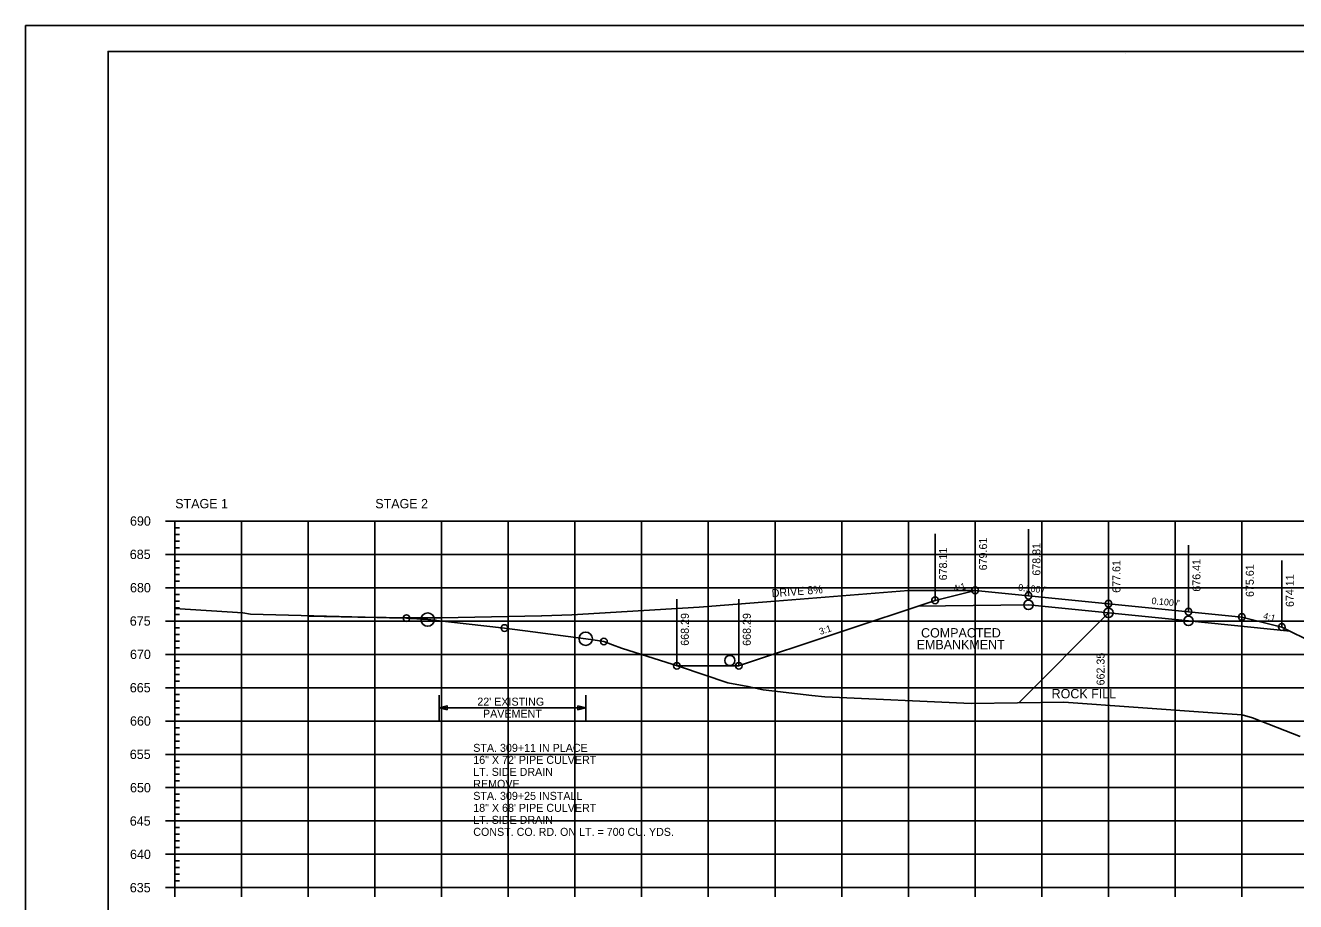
# Model space of a CAD drawing. Extents: x 1370515 to 1370849, y 383299 to 386073.
# Drawn here: x 1370515.4 to 1370705.9, y 384661.3 to 384792.8 of the extents above; entities that cross this region are included whole.
import ezdxf

# ---------------------------------------------------------------- set-up
doc = ezdxf.new("R2010")
doc.units = 0
for name, color, linetype in [('R_Alt Surface', 7, 'Continuous'), ('R_Axis', 7, 'Continuous'), ('R_Axis Annot', 7, 'Continuous'), ('R_Border', 7, 'Continuous'), ('R_Drive', 7, 'Continuous'), ('R_Exist Surface', 7, 'Continuous'), ('R_Fin Surface', 7, 'Continuous'), ('R_Grid', 7, 'Continuous'), ('R_No Plot', 7, 'Continuous'), ('R_ROW Annot', 7, 'Continuous'), ('R_Water', 7, 'Continuous'), ('R_Xsect Elev', 7, 'Continuous'), ('R_Xsect Slope', 7, 'Continuous')]:
    doc.layers.add(name, color=color, linetype=linetype)

msp = doc.modelspace()

# ---------------------------------------------------------------- linework, layer by layer
at = {"layer": 'R_Alt Surface'}
msp.add_lwpolyline([(1370649.23, 384705.69), (1370665.8, 384705.86), (1370677.8, 384704.67), (1370689.8, 384703.46), (1370705.03, 384701.93)], dxfattribs=at)
at = {"layer": 'R_Axis'}
for p, q in [((1370536.4, 384718.44), (1370539.2, 384718.44)), ((1370537.8, 384663.44), (1370537.8, 384718.44)), ((1370537.8, 384717.44), (1370538.5, 384717.44)), ((1370537.8, 384716.44), (1370538.5, 384716.44)), ((1370537.8, 384715.44), (1370538.5, 384715.44)), ((1370536.4, 384713.44), (1370539.2, 384713.44)), ((1370537.8, 384714.44), (1370538.5, 384714.44)), ((1370537.8, 384712.44), (1370538.5, 384712.44)), ((1370537.8, 384711.44), (1370538.5, 384711.44)), ((1370537.8, 384710.44), (1370538.5, 384710.44)), ((1370537.8, 384709.44), (1370538.5, 384709.44)), ((1370536.4, 384708.44), (1370539.2, 384708.44)), ((1370537.8, 384707.44), (1370538.5, 384707.44)), ((1370537.8, 384706.44), (1370538.5, 384706.44)), ((1370537.8, 384705.44), (1370538.5, 384705.44)), ((1370536.4, 384703.44), (1370539.2, 384703.44)), ((1370537.8, 384704.44), (1370538.5, 384704.44)), ((1370537.8, 384702.44), (1370538.5, 384702.44)), ((1370537.8, 384701.44), (1370538.5, 384701.44)), ((1370537.8, 384700.44), (1370538.5, 384700.44)), ((1370537.8, 384699.44), (1370538.5, 384699.44)), ((1370536.4, 384698.44), (1370539.2, 384698.44)), ((1370537.8, 384697.44), (1370538.5, 384697.44)), ((1370537.8, 384696.44), (1370538.5, 384696.44)), ((1370537.8, 384695.44), (1370538.5, 384695.44)), ((1370537.8, 384694.44), (1370538.5, 384694.44)), ((1370536.4, 384693.44), (1370539.2, 384693.44)), ((1370537.8, 384692.44), (1370538.5, 384692.44)), ((1370537.8, 384691.44), (1370538.5, 384691.44)), ((1370537.8, 384690.44), (1370538.5, 384690.44)), ((1370536.4, 384688.44), (1370539.2, 384688.44)), ((1370537.8, 384689.44), (1370538.5, 384689.44)), ((1370537.8, 384687.44), (1370538.5, 384687.44)), ((1370537.8, 384686.44), (1370538.5, 384686.44)), ((1370537.8, 384685.44), (1370538.5, 384685.44)), ((1370537.8, 384684.44), (1370538.5, 384684.44)), ((1370536.4, 384683.44), (1370539.2, 384683.44)), ((1370537.8, 384682.44), (1370538.5, 384682.44)), ((1370537.8, 384681.44), (1370538.5, 384681.44)), ((1370537.8, 384680.44), (1370538.5, 384680.44)), ((1370537.8, 384679.44), (1370538.5, 384679.44)), ((1370536.4, 384678.44), (1370539.2, 384678.44)), ((1370537.8, 384677.44), (1370538.5, 384677.44)), ((1370537.8, 384676.44), (1370538.5, 384676.44)), ((1370537.8, 384675.44), (1370538.5, 384675.44)), ((1370536.4, 384673.44), (1370539.2, 384673.44)), ((1370537.8, 384674.44), (1370538.5, 384674.44)), ((1370537.8, 384672.44), (1370538.5, 384672.44)), ((1370537.8, 384671.44), (1370538.5, 384671.44)), ((1370537.8, 384670.44), (1370538.5, 384670.44)), ((1370537.8, 384669.44), (1370538.5, 384669.44)), ((1370536.4, 384668.44), (1370539.2, 384668.44)), ((1370537.8, 384667.44), (1370538.5, 384667.44)), ((1370537.8, 384666.44), (1370538.5, 384666.44)), ((1370537.8, 384665.44), (1370538.5, 384665.44)), ((1370536.4, 384663.44), (1370539.2, 384663.44)), ((1370537.8, 384662.04), (1370537.8, 384664.84)), ((1370537.8, 384664.44), (1370538.5, 384664.44)), ((1370537.8, 384663.44), (1370817.8, 384663.44)), ((1370547.8, 384662.04), (1370547.8, 384664.84)), ((1370557.8, 384662.04), (1370557.8, 384664.84)), ((1370567.8, 384662.04), (1370567.8, 384664.84)), ((1370577.8, 384662.04), (1370577.8, 384664.84)), ((1370587.8, 384662.04), (1370587.8, 384664.84)), ((1370597.8, 384662.04), (1370597.8, 384664.84)), ((1370607.8, 384662.04), (1370607.8, 384664.84)), ((1370617.8, 384662.04), (1370617.8, 384664.84)), ((1370627.8, 384662.04), (1370627.8, 384664.84)), ((1370637.8, 384662.04), (1370637.8, 384664.84)), ((1370647.8, 384662.04), (1370647.8, 384664.84)), ((1370657.8, 384662.04), (1370657.8, 384664.84)), ((1370667.8, 384662.04), (1370667.8, 384664.84)), ((1370677.8, 384662.04), (1370677.8, 384664.84)), ((1370687.8, 384662.04), (1370687.8, 384664.84)), ((1370697.8, 384662.04), (1370697.8, 384664.84))]:
    msp.add_line(p, q, dxfattribs=at)
at = {"layer": 'R_Border'}
for p, q in [((1370527.8, 384788.9), (1370843.98, 384788.9)), ((1370527.8, 384583.44), (1370527.8, 384788.9)), ((1370680.32, 384788.64), (1370680.32, 384788.64)), ((1370680.32, 384788.64), (1370680.32, 384788.64))]:
    msp.add_line(p, q, dxfattribs=at)
at = {"layer": 'R_Exist Surface'}
msp.add_lwpolyline([(1370537.8, 384705.3), (1370547.98, 384704.66), (1370549.17, 384704.49), (1370562.44, 384704.13), (1370569.97, 384703.9), (1370572.53, 384703.88), (1370573.25, 384703.83), (1370575.72, 384703.66), (1370578.86, 384703.31), (1370587.24, 384702.39), (1370591.5, 384701.82), (1370599.41, 384700.78), (1370600.55, 384700.6), (1370602.15, 384700.36), (1370603.45, 384699.89), (1370604.76, 384699.37), (1370613.46, 384696.61), (1370620.74, 384694.16), (1370623.75, 384693.64), (1370626.02, 384693.13), (1370633.34, 384692.26), (1370635.29, 384692.09), (1370657.23, 384691.09), (1370671.09, 384691.27), (1370693.42, 384689.68), (1370697.83, 384689.35), (1370699.42, 384688.92), (1370706.55, 384686.11)], dxfattribs=at)
at = {"layer": 'R_Fin Surface'}
msp.add_line((1370677.82, 384704.66), (1370664.34, 384691.18), dxfattribs=at)
for points in [[(1370557.68, 384704.17), (1370565.23, 384704.03), (1370566.35, 384704.01), (1370572.7, 384703.93), (1370573.22, 384703.93), (1370577.56, 384703.92), (1370577.79, 384703.92), (1370592.76, 384704.2), (1370592.8, 384704.2), (1370592.81, 384704.2), (1370597.35, 384704.37), (1370616.41, 384705.53), (1370627.8, 384706.44), (1370647.8, 384708.04), (1370657.8, 384708.04)], [(1370613.08, 384696.73), (1370622.35, 384696.73), (1370651.8, 384706.54), (1370657.8, 384708.04), (1370665.8, 384707.24), (1370677.8, 384706.04), (1370689.8, 384704.84), (1370697.8, 384704.04), (1370703.8, 384702.54), (1370708.65, 384700.12), (1370747.82, 384680.53)]]:
    msp.add_lwpolyline(points, dxfattribs=at)
at = {"layer": 'R_Grid'}
for p, q in [((1370537.8, 384718.44), (1370817.8, 384718.44)), ((1370537.8, 384663.44), (1370537.8, 384718.44)), ((1370547.8, 384663.44), (1370547.8, 384718.44)), ((1370557.8, 384663.44), (1370557.8, 384718.44)), ((1370567.8, 384663.44), (1370567.8, 384718.44)), ((1370577.8, 384663.44), (1370577.8, 384718.44)), ((1370587.8, 384663.44), (1370587.8, 384718.44)), ((1370597.8, 384663.44), (1370597.8, 384718.44)), ((1370607.8, 384663.44), (1370607.8, 384718.44)), ((1370617.8, 384663.44), (1370617.8, 384718.44)), ((1370627.8, 384663.44), (1370627.8, 384718.44)), ((1370637.8, 384663.44), (1370637.8, 384718.44)), ((1370647.8, 384663.44), (1370647.8, 384718.44)), ((1370657.8, 384663.44), (1370657.8, 384718.44)), ((1370667.8, 384663.44), (1370667.8, 384718.44)), ((1370677.8, 384663.44), (1370677.8, 384718.44)), ((1370687.8, 384663.44), (1370687.8, 384718.44)), ((1370697.8, 384663.44), (1370697.8, 384718.44)), ((1370537.8, 384713.44), (1370817.8, 384713.44)), ((1370537.8, 384708.44), (1370817.8, 384708.44)), ((1370537.8, 384703.44), (1370817.8, 384703.44)), ((1370537.8, 384698.44), (1370817.8, 384698.44)), ((1370537.8, 384693.44), (1370817.8, 384693.44)), ((1370537.8, 384688.44), (1370817.8, 384688.44)), ((1370537.8, 384683.44), (1370817.8, 384683.44)), ((1370537.8, 384678.44), (1370817.8, 384678.44)), ((1370537.8, 384673.44), (1370817.8, 384673.44)), ((1370537.8, 384668.44), (1370817.8, 384668.44)), ((1370537.8, 384663.44), (1370817.8, 384663.44))]:
    msp.add_line(p, q, dxfattribs=at)
at = {"layer": 'R_No Plot'}
msp.add_line((1370515.4, 384792.79), (1370848.73, 384792.79), dxfattribs=at)
for points in [[(1370515.39, 384792.79), (1370848.73, 384792.79), (1370848.73, 384579.45), (1370515.39, 384579.45)], [(1370761.72, 384788.9), (1370761.72, 384779.02), (1370797.45, 384779.02), (1370797.45, 384776.1), (1370820.65, 384776.1), (1370820.65, 384752.88), (1370843.98, 384752.88), (1370843.98, 384583.44), (1370527.8, 384583.44), (1370527.8, 384788.9)]]:
    msp.add_lwpolyline(points, close=True, dxfattribs=at)
for centre, radius in [((1370651.8, 384706.54), 0.5), ((1370651.8, 384706.54), 0.5), ((1370657.8, 384708.04), 0.5), ((1370665.8, 384707.24), 0.5), ((1370665.8, 384705.86), 0.7), ((1370677.8, 384704.67), 0.7), ((1370677.8, 384704.67), 0.7), ((1370677.8, 384706.04), 0.5), ((1370689.8, 384704.84), 0.5), ((1370572.53, 384703.88), 0.5), ((1370575.72, 384703.66), 1), ((1370689.8, 384703.46), 0.7), ((1370697.8, 384704.04), 0.5), ((1370587.24, 384702.39), 0.5), ((1370599.41, 384700.78), 1), ((1370703.8, 384702.54), 0.5), ((1370703.8, 384702.54), 0.5), ((1370602.15, 384700.36), 0.5), ((1370613.08, 384696.73), 0.5), ((1370622.37, 384696.72), 0.5)]:
    msp.add_circle(centre, radius, dxfattribs=at)
at = {"layer": 'R_ROW Annot'}
for p, q in [((1370577.43, 384688.56), (1370577.43, 384692.32)), ((1370599.43, 384688.56), (1370599.43, 384692.32)), ((1370599.43, 384690.44), (1370577.43, 384690.44))]:
    msp.add_line(p, q, dxfattribs=at)
for points in [[(1370578.63, 384690.14), (1370577.43, 384690.44), (1370578.63, 384690.74)], [(1370598.23, 384690.74), (1370599.43, 384690.44), (1370598.23, 384690.14)]]:
    msp.add_lwpolyline(points, close=True, dxfattribs=at)
at = {"layer": 'R_Water'}
msp.add_line((1370613.1, 384696.72), (1370622.37, 384696.72), dxfattribs=at)
msp.add_circle((1370621.03, 384697.52), 0.75, dxfattribs=at)
at = {"layer": 'R_Xsect Elev'}
for p, q in [((1370657.8, 384708.04), (1370657.8, 384718.04)), ((1370665.8, 384707.24), (1370665.8, 384717.24)), ((1370651.8, 384706.54), (1370651.8, 384716.54)), ((1370677.8, 384704.67), (1370677.8, 384714.67)), ((1370689.8, 384704.84), (1370689.8, 384714.84)), ((1370697.8, 384704.04), (1370697.8, 384714.04)), ((1370703.8, 384702.54), (1370703.8, 384712.54)), ((1370613.08, 384696.73), (1370613.08, 384706.73)), ((1370622.37, 384696.72), (1370622.37, 384706.72)), ((1370677.82, 384690.78), (1370677.82, 384700.78))]:
    msp.add_line(p, q, dxfattribs=at)

# ---------------------------------------------------------------- texts
at = {"layer": 'R_Axis'}
msp.add_text('-', height=0.0001, dxfattribs=at).set_placement((1370537.8, 384663.44))
at = {"layer": 'R_Axis Annot'}
for s, p in [('STAGE 1', (1370537.86, 384720.35)), ('STAGE 2', (1370567.86, 384720.35)), ('690', (1370531.08, 384717.74)), ('685', (1370531.05, 384712.74)), ('680', (1370531.08, 384707.74)), ('675', (1370531.05, 384702.74)), ('COMPACTED', (1370649.7, 384700.97)), ('EMBANKMENT', (1370649.04, 384699.21)), ('670', (1370531.08, 384697.74)), ('665', (1370531.05, 384692.74)), ('ROCK FILL', (1370669.28, 384691.84)), ('660', (1370531.08, 384687.74)), ('655', (1370531.05, 384682.74)), ('650', (1370531.08, 384677.74)), ('645', (1370531.05, 384672.74)), ('640', (1370531.08, 384667.74)), ('635', (1370531.05, 384662.74))]:
    msp.add_text(s, height=1.4, dxfattribs=at).set_placement(p)
at = {"layer": 'R_Drive'}
msp.add_text('DRIVE 8%', height=1.2, rotation=4.5739, dxfattribs=at).set_placement((1370627.35, 384707))
for s, p in [('STA. 309+11 IN PLACE', (1370582.55, 384683.81)), ('16" X 72\' PIPE CULVERT', (1370582.55, 384682.01)), ('LT. SIDE DRAIN', (1370582.55, 384680.21)), ('REMOVE ', (1370582.55, 384678.41)), ('STA. 309+25 INSTALL', (1370582.55, 384676.61)), ('18" X 68\' PIPE CULVERT', (1370582.55, 384674.81)), ('LT. SIDE DRAIN', (1370582.55, 384673.01)), ('CONST. CO. RD. ON LT. = 700 CU. YDS.', (1370582.55, 384671.21))]:
    msp.add_text(s, height=1.2, dxfattribs=at).set_placement(p)
at = {"layer": 'R_No Plot'}
for p in [(1370549.13, 384704.44), (1370604.71, 384699.32), (1370620.7, 384694.11), (1370625.98, 384693.08), (1370635.25, 384692.04), (1370671.04, 384691.22), (1370697.78, 384689.3)]:
    msp.add_text('+', height=0.1, dxfattribs=at).set_placement(p)
at = {"layer": 'R_ROW Annot'}
for s, p in [("22' EXISTING", (1370583.16, 384690.74)), ('PAVEMENT', (1370584.01, 384688.94))]:
    msp.add_text(s, height=1.2, dxfattribs=at).set_placement(p)
at = {"layer": 'R_Xsect Elev'}
for s, p in [('679.61', (1370659.6, 384711.04)), ('678.81', (1370667.6, 384710.24)), ('678.11', (1370653.6, 384709.54)), ('677.61', (1370679.6, 384707.67)), ('676.41', (1370691.6, 384707.84)), ('675.61', (1370699.6, 384707.04)), ('674.11', (1370705.6, 384705.54)), ('668.29', (1370614.88, 384699.73)), ('668.29', (1370624.17, 384699.72)), ('662.35', (1370677.22, 384693.78))]:
    msp.add_text(s, height=1.2, rotation=90, dxfattribs=at).set_placement(p)
at = {"layer": 'R_Xsect Slope'}
for s, rotation, p in [('4:1', 14.0362, (1370654.68, 384707.78)), ("0.100'/'", 354.2894, (1370664.23, 384708)), ("0.100'/'", 354.2894, (1370684.23, 384706)), ('4:1', 345.9638, (1370700.92, 384703.78)), ('3:1', 18.4349, (1370634.6, 384701.34))]:
    msp.add_text(s, height=1, rotation=rotation, dxfattribs=at).set_placement(p)

doc.saveas('drawing.dxf')
